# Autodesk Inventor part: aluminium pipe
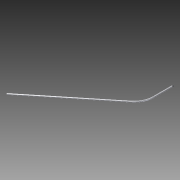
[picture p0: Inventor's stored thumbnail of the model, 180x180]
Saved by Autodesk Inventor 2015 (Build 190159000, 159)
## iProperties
Created: 2015-02
Part Number: aluminium pipe
Material: Generic
Document SubType Name: Modeling
Designer: sungeun
Density: 1 g/cm^3
Appearance: Default
Author: sungeun
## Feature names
1. Sweep1
## Parameters: d1 = 50 deg, d4 = 12.7 mm, d6 = 0, d7 = 0, d8 = 15 mm, d9 = 0
